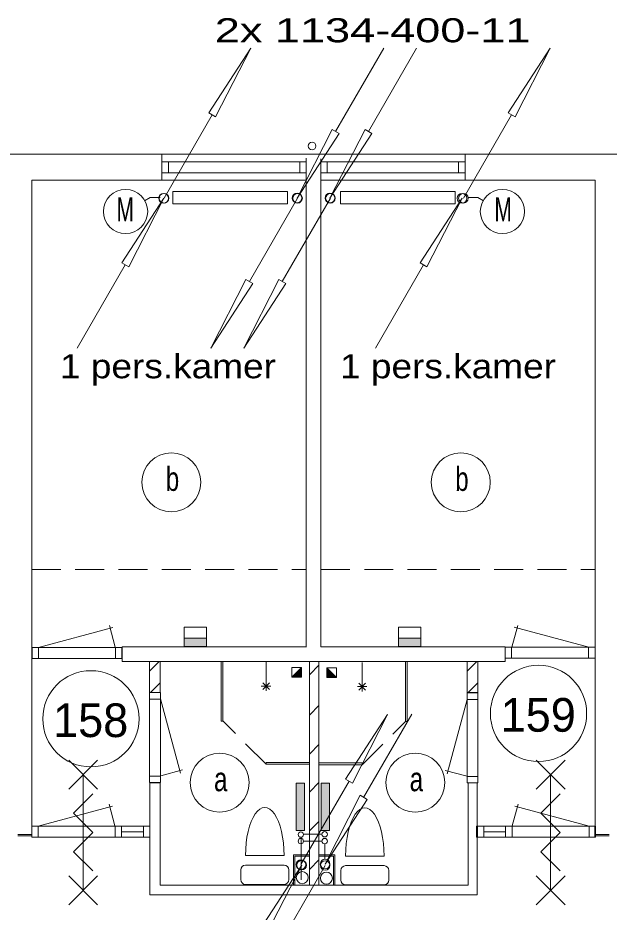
# Model space of a CAD drawing. Extents: x 295824 to 414724, y 24924 to 109024.
# Drawn here: x 313944 to 320086, y 71286 to 80577 of the extents above; entities that cross this region are included whole.
import ezdxf
from ezdxf.enums import TextEntityAlignment as Align

# ---------------------------------------------------------------- set-up
doc = ezdxf.new("R2010")
doc.units = 0
doc.header["$LTSCALE"] = 100
doc.linetypes.add('LONG_DASHED', pattern=[7.5, 6, -1.5])
doc.linetypes.add('MEDIUM_DASHED', pattern=[4.5, 3, -1.5])
doc.layers.add('16', color=7, linetype='Continuous', lineweight=13)
doc.layers.add('61', color=7, linetype='Continuous', lineweight=13)

msp = doc.modelspace()

# ---------------------------------------------------------------- hatches: boundary and pattern name
at = {"layer": '16'}
for points in [[(315902.2, 74047.1), (315670.7, 74047.1), (315670.7, 74133.6), (315902.2, 74133.6)], [(318129.9, 74047.1), (317898.4, 74047.1), (317898.4, 74133.6), (318129.9, 74133.6)], [(316835.4, 72625.1), (316920.8, 72625.1), (316920.8, 72132.9), (316835.4, 72132.9)], [(317094.6, 72625.1), (317180, 72625.1), (317180, 72132.9), (317094.6, 72132.9)]]:
    msp.add_hatch(color=256, dxfattribs=at).paths.add_polyline_path(points)
at = {"layer": '61'}
for points in [[(316790.6, 73728.2), (316890.6, 73828.2), (316890.6, 73728.2)], [(317253, 73722.8), (317153, 73822.8), (317153, 73722.8)]]:
    msp.add_hatch(color=256, dxfattribs=at).paths.add_polyline_path(points)

# ---------------------------------------------------------------- linework, layer by layer
at = {"layer": '16'}
for p, q in [((317744.5, 80264.3), (317244.5, 79398.3)), ((318086.1, 80264.3), (317586.1, 79398.3)), ((315462.6, 78704.2), (315962.6, 79570.2)), ((318572.9, 78704.2), (319072.9, 79570.2)), ((316849.4, 78703.1), (316349.4, 77837.1)), ((317191, 78703.1), (316691, 77837.1)), ((314559.2, 77144.1), (315059.2, 78010.1)), ((317657.6, 77144.1), (318157.6, 78010.1)), ((315670.7, 74133.6), (315670.7, 74247.5)), ((317898.4, 74133.6), (317898.4, 74247.5)), ((318035.8, 73344.2), (317535.8, 72478.2)), ((316884.2, 71779.2), (317384.2, 72645.2)), ((316887.6, 71622.2), (316887.6, 72062.3)), ((317103, 72094.1), (316911.2, 72094.1)), ((317136.2, 71769.9), (316636.2, 70903.9))]:
    msp.add_line(p, q, dxfattribs=at)
at = {"layer": '16', "linetype": 'LONG_DASHED'}
for p, q in [((316911.4, 72023.4), (317102.9, 72023.4)), ((317133.8, 71834), (317133.8, 71997.6))]:
    msp.add_line(p, q, dxfattribs=at)
at = {"layer": '16'}
for points in [[(316362.6, 80263.2), (315998.6, 79549.2), (315926.6, 79591.2)], [(319472.9, 80263.2), (319108.9, 79549.2), (319036.9, 79591.2)], [(316844.5, 78705.3), (317208.5, 79419.3), (317280.5, 79377.3)], [(317186.1, 78705.3), (317550.1, 79419.3), (317622.1, 79377.3)], [(315459.2, 78703.1), (315095.2, 77989.1), (315023.2, 78031.1)], [(315553.4, 78644.2), (316743.3, 78644.2), (316743.3, 78773.8), (315553.4, 78773.8)], [(317297, 78644.2), (318486.9, 78644.2), (318486.9, 78773.8), (317297, 78773.8)], [(318557.6, 78703.1), (318193.6, 77989.1), (318121.6, 78031.1)], [(315949.4, 77144.1), (316313.4, 77858.1), (316385.4, 77816.1)], [(316291, 77144.1), (316655, 77858.1), (316727, 77816.1)], [(315902.2, 74047.1), (315670.7, 74047.1), (315670.7, 74133.6), (315902.2, 74133.6)], [(318129.9, 74047.1), (317898.4, 74047.1), (317898.4, 74133.6), (318129.9, 74133.6)], [(317784.2, 73338.2), (317420.2, 72624.2), (317348.2, 72666.2)], [(316835.4, 72625.1), (316920.8, 72625.1), (316920.8, 72132.9), (316835.4, 72132.9)], [(317094.6, 72625.1), (317180, 72625.1), (317180, 72132.9), (317094.6, 72132.9)], [(317135.8, 71785.2), (317499.8, 72499.2), (317571.8, 72457.2)], [(316892.3, 71774), (316528.3, 71060), (316456.3, 71102)]]:
    msp.add_lwpolyline(points, close=True, dxfattribs=at)
for points in [[(315423.8, 78710.9), (315317.8, 78710.9), (315258.3, 78676.5)], [(318616.5, 78710.9), (318722.6, 78710.9), (318782.1, 78676.5)], [(315902.2, 74133.6), (315902.2, 74247.5), (315670.7, 74247.5)], [(318129.9, 74133.6), (318129.9, 74247.5), (317898.4, 74247.5)]]:
    msp.add_lwpolyline(points, dxfattribs=at)
for centre, radius in [((315062.7, 78565.5), 229.9), ((318977.7, 78565.5), 229.9), ((315459.1, 78702.8), 50), ((315462.6, 78703.9), 50), ((316844.5, 78705.6), 50), ((316849.4, 78703.4), 50), ((317186.1, 78705.6), 50), ((317191, 78703.4), 50), ((318557.6, 78702.8), 50), ((318572.9, 78703.9), 50), ((316883.5, 72091.2), 27.9), ((317130.9, 72094.1), 27.9), ((316883.5, 72023.4), 27.9), ((317130.9, 72023.4), 27.9), ((316884.2, 71778.9), 50), ((317135.8, 71785.5), 50), ((316892.3, 71773.7), 50), ((317136.2, 71770.2), 50)]:
    msp.add_circle(centre, radius, dxfattribs=at)
at = {"layer": '61'}
for p, q in [((315441, 78890.7), (315441, 79160.7)), ((315508, 78969), (315508, 79082.9)), ((316873.1, 78968.4), (316873.1, 79082.4)), ((316940.1, 79118.1), (316940.1, 74040.8)), ((317090.1, 79114.3), (317090.1, 74040.8)), ((317156.6, 78969.4), (317156.6, 79083.4)), ((318520.9, 78969.1), (318520.9, 79082.7)), ((318589.5, 78890.8), (318589.5, 79160.8)), ((314090.1, 78890.8), (316940.1, 78890.8)), ((314090.1, 72179.8), (314090.1, 78890.8)), ((319940.1, 78890.8), (317090.1, 78890.8)), ((319940.1, 72179.8), (319940.1, 78890.8)), ((314157.5, 74036.8), (314930.2, 74243.8)), ((314955.9, 74037.4), (314895.1, 74264.3)), ((319075.3, 74038.5), (319136, 74265.4)), ((319873.7, 74037.9), (319100.9, 74244.9)), ((314158.2, 73922.2), (314158.2, 74036.2)), ((314958.2, 73922.2), (314958.2, 74036.2)), ((315025.2, 73922.2), (315025.2, 74036.2)), ((319005.9, 73923.2), (319005.9, 74037.2)), ((319072.9, 73923.2), (319072.9, 74037.2)), ((319872.9, 73923.2), (319872.9, 74037.2)), ((315310.4, 73789.9), (315410.1, 73889.6)), ((315311.9, 73566.1), (315311.9, 73890.2)), ((315311.9, 73890.2), (315421.9, 73890.2)), ((315421.9, 73566.1), (315421.9, 73890.2)), ((316073.1, 73890.5), (316073.1, 73270)), ((316523, 73684), (316523, 73884)), ((316975, 73890.8), (316975, 71565.8)), ((317071.3, 73890.8), (317071.3, 71565.8)), ((317520.7, 73678.6), (317520.7, 73878.6)), ((317970.5, 73885.1), (317970.5, 73264.6)), ((318610.9, 73566.1), (318610.9, 73890.2)), ((318610.9, 73890.2), (318720.8, 73890.2)), ((318612.6, 73789.9), (318712.3, 73889.6)), ((318720.8, 73566.1), (318720.8, 73890.2)), ((316975.5, 73754.6), (317071.3, 73850.4)), ((316523, 73684), (316523, 73584)), ((315322.7, 73567.3), (315422.4, 73667)), ((316573, 73634), (316473, 73634)), ((316558.3, 73669.3), (316487.6, 73598.6)), ((316558.3, 73598.6), (316487.6, 73669.3)), ((317470.7, 73628.6), (317570.7, 73628.6)), ((317485.3, 73664), (317556, 73593.3)), ((317485.3, 73593.3), (317556, 73664)), ((317520.7, 73678.6), (317520.7, 73578.6)), ((318621.2, 73567.3), (318720.9, 73667)), ((315310.1, 73565.2), (315310.1, 72632.8)), ((315310.1, 73499.8), (315424.1, 73499.8)), ((315311.9, 73566.1), (315421.9, 73566.1)), ((315427.3, 73500.6), (315634.3, 72727.8)), ((318610.2, 73562.6), (318724.2, 73562.6)), ((318610.9, 73566.1), (318720.8, 73566.1)), ((318723.6, 73562.6), (318723.6, 72628.6)), ((316975.5, 73336.5), (317071.3, 73432.3)), ((318611.5, 73496.3), (318404.4, 72723.6)), ((318723.6, 73495.6), (318609.6, 73495.6)), ((316975.5, 72931.9), (317071.3, 73027.7)), ((314772.1, 72863), (314472.1, 72563)), ((314472.1, 72863), (314772.1, 72563)), ((319628, 72863), (319328, 72563)), ((319328, 72863), (319628, 72563)), ((315427.9, 72702.2), (315654.8, 72762.9)), ((316973.2, 72840.5), (316524, 72840.5)), ((316524, 72822.5), (316524, 72840.5)), ((316973.5, 72822.5), (316524, 72822.5)), ((317070.2, 72817.1), (317519.6, 72817.1)), ((317070.5, 72835.1), (317519.6, 72835.1)), ((317519.6, 72817.1), (317519.6, 72835.1)), ((318610.9, 72697.9), (318384, 72758.7)), ((314622.1, 71513), (314622.1, 72713)), ((315310.1, 72699.8), (315424.1, 72699.8)), ((318723.6, 72695.6), (318609.6, 72695.6)), ((319478, 71513), (319478, 72713)), ((315316.1, 72629.2), (315316.1, 72063.4)), ((315316.1, 72629.2), (315421.3, 72629.2)), ((316975.5, 72535.9), (317071.3, 72631.7)), ((318621.3, 72627.8), (318621.3, 71565.8)), ((318621.3, 72627.8), (318716.1, 72627.8)), ((318716.1, 72627.8), (318716.1, 72165.8)), ((314154.1, 72180.4), (314926.8, 72387.5)), ((314952.5, 72181), (314891.7, 72407.9)), ((319079.8, 72181.1), (319140.6, 72407.9)), ((319878.3, 72180.4), (319105.5, 72387.5)), ((316975.5, 72132.6), (317071.3, 72228.3)), ((314154.9, 72065.8), (314154.9, 72179.8)), ((314954.9, 72065.8), (314954.9, 72179.8)), ((315021.9, 72065.8), (315021.9, 72179.8)), ((315247.9, 72119.9), (315021.9, 72119.9)), ((315247.9, 72065.8), (315247.9, 72179.8)), ((318784.5, 72065.8), (318784.5, 72179.8)), ((318784.5, 72119.9), (319010.5, 72119.9)), ((319010.5, 72065.8), (319010.5, 72179.8)), ((319077.5, 72065.8), (319077.5, 72179.8)), ((319877.5, 72065.8), (319877.5, 72179.8)), ((313944.8, 72092.1), (314086, 72092.1)), ((313944.8, 72077.1), (314086, 72077.1)), ((319943.6, 72092.1), (320084.8, 72092.1)), ((319943.6, 72077.1), (320084.8, 72077.1)), ((316708.7, 71873.6), (316308.7, 71873.6)), ((316821.2, 71866.2), (316971.2, 71866.2)), ((316821.2, 71566.2), (316821.2, 71866.2)), ((316975.5, 71731.7), (317071.3, 71827.4)), ((317071.3, 71865.8), (317221.3, 71865.8)), ((317221.3, 71865.8), (317221.3, 71565.8)), ((317748.1, 71868.7), (317348.1, 71868.7)), ((316308.7, 71773.6), (316708.7, 71773.6)), ((317348.1, 71768.7), (317748.1, 71768.7)), ((314772.1, 71663), (314472.1, 71363)), ((314472.1, 71663), (314772.1, 71363)), ((316258.7, 71623.6), (316258.7, 71723.6)), ((316758.7, 71723.6), (316758.7, 71623.6)), ((317298.1, 71618.7), (317298.1, 71718.7)), ((317798.1, 71718.7), (317798.1, 71618.7)), ((319628, 71663), (319328, 71363)), ((319328, 71663), (319628, 71363)), ((316708.7, 71573.6), (316308.7, 71573.6)), ((317748.1, 71568.7), (317348.1, 71568.7))]:
    msp.add_line(p, q, dxfattribs=at)
at = {"layer": '61', "linetype": 'MEDIUM_DASHED'}
for p, q in [((314090.7, 74844.1), (316939.8, 74844.1)), ((317093.1, 74844.1), (319940.1, 74844.1)), ((316522, 72822.9), (316075.1, 73269.8)), ((317521.7, 72817.6), (317968.6, 73264.5))]:
    msp.add_line(p, q, dxfattribs=at)
at = {"layer": '61'}
for points in [[(301796.6, 66927.7), (301820.1, 79160.8), (332210.1, 79160.8)], [(314091.2, 73922.2), (314091.2, 74036.2), (315025.2, 74036.2)], [(315025.2, 73922.2), (314091.2, 73922.2), (314091.2, 74036.2)], [(316941.1, 74040.8), (315026, 74040.8), (315026, 73890.8), (319005.4, 73890.8)], [(317091.1, 74040.8), (319005.4, 74040.8), (319005.4, 73890.8)], [(319939.9, 73923.2), (319939.9, 74037.2), (319005.9, 74037.2)], [(319005.9, 73923.2), (319939.9, 73923.2), (319939.9, 74037.2)], [(316055.1, 73890.5), (316055.1, 73270), (316073.1, 73270)], [(317988.5, 73885.1), (317988.5, 73264.6), (317970.5, 73264.6)], [(316890.6, 73828.2), (316890.6, 73728.2), (316790.6, 73728.2)], [(317153, 73822.8), (317153, 73722.8), (317253, 73722.8)], [(315421.3, 72629.2), (315421.3, 71565.8), (318621.3, 71565.8)], [(314722.1, 71713), (314522.1, 71913), (314722.1, 72113), (314522.1, 72313), (314722.1, 72513)], [(319578, 71713), (319378, 71913), (319578, 72113), (319378, 72313), (319578, 72513)], [(315316.1, 72065.8), (315316.1, 71465.8), (318716.1, 71465.8), (318716.1, 72065.8)], [(316806.2, 71566.2), (316806.2, 71881.2), (316971.2, 71881.2)], [(317071.3, 71880.8), (317236.3, 71880.8), (317236.3, 71565.8)]]:
    msp.add_lwpolyline(points, dxfattribs=at)
for points in [[(315441.2, 78968.9), (315441.2, 79082.9), (316939.9, 79082.9), (316939.9, 78968.9)], [(317090.2, 78969.1), (317090.2, 79083.1), (318589.6, 79083.1), (318589.6, 78969.1)], [(316890.6, 73828.2), (316790.6, 73828.2), (316790.6, 73728.2)], [(316790.6, 73728.2), (316890.6, 73828.2), (316890.6, 73728.2)], [(317153, 73822.8), (317253, 73822.8), (317253, 73722.8)], [(317253, 73722.8), (317153, 73822.8), (317153, 73722.8)], [(315310.1, 72631.9), (315424.1, 72631.9), (315424.1, 73565.9), (315310.1, 73565.9)], [(318723.6, 73562.6), (318723.6, 72628.6), (318609.6, 72628.6), (318609.6, 73562.6)], [(314087.9, 72065.8), (314087.9, 72179.8), (315314.2, 72179.8), (315314.2, 72065.8)], [(314087.9, 72065.8), (314087.9, 72179.8), (315314.2, 72179.8), (315314.2, 72065.8)], [(318709.2, 72065.8), (318709.2, 72179.8), (319936.2, 72179.8), (319936.2, 72065.8)], [(318717.5, 72065.8), (318717.5, 72179.8), (319944.5, 72179.8), (319944.5, 72065.8)]]:
    msp.add_lwpolyline(points, close=True, dxfattribs=at)
for centre, radius in [((317000.1, 79245.8), 40), ((315538.5, 75751.7), 306.3), ((318545.3, 75751.7), 306.3), ((314703, 73294.4), 500), ((319352.5, 73350.1), 500), ((316039.7, 72631.2), 306.3), ((318072, 72631.2), 306.3), ((316898.8, 71643.7), 62.5), ((317148.8, 71638.2), 62.5)]:
    msp.add_circle(centre, radius, dxfattribs=at)
for centre, start, end in [((316308.7, 71723.6), 90, 180), ((316708.7, 71723.6), 0, 90), ((317348.1, 71718.7), 90, 180), ((317748.1, 71718.7), 0, 90), ((316308.7, 71623.6), 180, 270), ((316708.7, 71623.6), 270, 0), ((317348.1, 71618.7), 180, 270), ((317748.1, 71618.7), 270, 0)]:
    msp.add_arc(centre, 50, start, end, dxfattribs=at)
for centre in [(316508.7, 71873.6), (317548.1, 71868.7)]:
    msp.add_ellipse(centre, major_axis=(0, 500), ratio=0.4, start_param=4.712389, end_param=7.853982, dxfattribs=at)

# ---------------------------------------------------------------- texts
at = {"layer": '16'}
for s, width, p in [('2x 1134-400-11', 1.4, (315990.2, 80323.7)), ('M', 0.65, (314968.7, 78462.5)), ('M', 0.65, (318894.5, 78462.5))]:
    msp.add_text(s, height=250, dxfattribs=dict(at, width=width)).set_placement(p)
at = {"layer": '61'}
for s, width, p in [('1 pers.kamer', 1.15, (314381.4, 76832.7)), ('1 pers.kamer', 1.15, (317290.6, 76832.7)), ('b', 0.75, (315480.5, 75662.5)), ('b', 0.75, (318487.3, 75662.5)), ('a', 0.75, (315981.7, 72542)), ('a', 0.75, (318014, 72542))]:
    msp.add_text(s, height=250, dxfattribs=dict(at, width=width)).set_placement(p)
for s, p in [('159', (319349.6, 73160.2)), ('158', (314700.1, 73104.5))]:
    msp.add_text(s, height=350, dxfattribs=at).set_placement(p, align=Align.CENTER)

doc.saveas('drawing.dxf')
